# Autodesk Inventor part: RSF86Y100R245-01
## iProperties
Created: 2007-10
Part Number: RSF86Y100R245-01
Material: 1.0037 St 37-2
Document SubType Name: Modellieren
Designer: TMT
Manufacturer: Standard
Standards Organization: Custom
Density: 7.85 g/cm^3
Mass: 92.8546 g
Surface Area: 37.6615 cm^2
Volume: 11.8286 cm^3
Author: TMT
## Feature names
1. Extrusion2
2. Extrusion3
3. Extrusion4
4. Extrusion5
5. Extrusion6
6. Extrusion7
